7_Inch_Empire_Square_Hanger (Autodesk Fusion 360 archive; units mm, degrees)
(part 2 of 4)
sketch "Angular_Hip_Valley" plane through (0, 0, 0) normal (0, 1, 0) x axis (1, 0, 0)
  line L1 (38.1, -88.7211) -> (122.0586, -4.7625)
  line L2 (0, 1.5875) -> (0, -176.2125)
  line L3 (177.8, 1.5875) -> (0, 1.5875)
  line L4 (0, -176.2125) -> (177.8, 1.5875)
  line L5 (38.1, -97.7013) -> (38.1, -88.7211)
  line L6 (131.0388, -4.7625) -> (38.1, -97.7013)
  line L7 (122.0586, -4.7625) -> (131.0388, -4.7625)
  line L8 (113.4532, -13.3678) -> (0, 0)
  line L9 (116.5241, -10.297) -> (0, 0)
  line L10 (107.7616, -19.0595) -> (0, 0)
  line L11 (102.6349, -24.1862) -> (0, 0)
  line L12 (97.9544, -28.8667) -> (0, 0)
  line L13 (93.6966, -33.1245) -> (0, 0)
  line L14 (89.7798, -37.0412) -> (0, 0)
  line L15 (86.1898, -40.6313) -> (0, 0)
  line L16 (82.8697, -43.9514) -> (0, 0)
  line L17 (79.7978, -47.0233) -> (0, 0)
  line L18 (76.9467, -49.8744) -> (0, 0)
  line L19 (74.2837, -52.5374) -> (0, 0)
  line L20 (71.815, -55.0061) -> (0, 0)
  line L21 (69.4939, -57.3271) -> (0, 0)
  line L22 (67.3222, -59.4989) -> (0, 0)
  line L23 (65.2814, -61.5396) -> (0, 0)
  line L24 (63.3552, -63.4659) -> (0, 0)
  line L25 (61.5396, -65.2814) -> (0, 0)
  line L26 (59.832, -66.9891) -> (0, 0)
  line L27 (58.2084, -68.6127) -> (0, 0)
  line L28 (56.6787, -70.1424) -> (0, 0)
  line L29 (55.2312, -71.5899) -> (0, 0)
  line L30 (53.8432, -72.9778) -> (0, 0)
  line L31 (52.526, -74.2951) -> (0, 0)
  line L32 (36.3039, -86.925) -> (120.2625, -2.9664)
  line L33 (34.5079, -85.129) -> (118.4665, -1.1704)
  line L34 (107.0263, -12.6106) -> (113.4532, -13.3678)
  line L35 (109.9232, -9.7137) -> (116.5241, -10.297)
  line L36 (101.6571, -17.9798) -> (107.7616, -19.0595)
  line L37 (96.8208, -22.8161) -> (102.6349, -24.1862)
  line L38 (92.4054, -27.2315) -> (97.9544, -28.8667)
  line L39 (88.3888, -31.2481) -> (93.6966, -33.1245)
  line L40 (84.694, -34.9429) -> (89.7798, -37.0412)
  line L41 (81.3072, -38.3296) -> (86.1898, -40.6313)
  line L42 (78.1753, -41.4616) -> (82.8697, -43.9514)
  line L43 (75.2774, -44.3595) -> (79.7978, -47.0233)
  line L44 (72.5878, -47.0491) -> (76.9467, -49.8744)
  line L45 (70.0756, -49.5613) -> (74.2837, -52.5374)
  line L46 (67.7468, -51.8901) -> (71.815, -55.0061)
  line L47 (65.5572, -54.0797) -> (69.4939, -57.3271)
  line L48 (63.5085, -56.1284) -> (67.3222, -59.4989)
  line L49 (61.5834, -58.0535) -> (65.2814, -61.5396)
  line L50 (59.7662, -59.8706) -> (63.3552, -63.4659)
  line L51 (58.0535, -61.5834) -> (61.5396, -65.2814)
  line L52 (56.4427, -63.1942) -> (59.832, -66.9891)
  line L53 (54.911, -64.7259) -> (58.2084, -68.6127)
  line L54 (53.4679, -66.169) -> (56.6787, -70.1424)
  line L55 (52.1025, -67.5344) -> (55.2312, -71.5899)
  line L56 (50.7931, -68.8438) -> (53.8432, -72.9778)
  line L57 (49.5505, -70.0864) -> (52.526, -74.2951)
  line L58 (117.1566, -10.3529) -> (109.9232, -9.7137)
  line L59 (109.9511, -9.3974) -> (117.1846, -10.0366)
  line L60 (117.1287, -10.6692) -> (109.8952, -10.03)
  line L61 (114.0839, -13.4422) -> (107.0263, -12.6106)
  line L62 (107.0635, -12.2953) -> (114.121, -13.1268)
  line L63 (114.0467, -13.7575) -> (106.9892, -12.9259)
  line L64 (108.3869, -19.1701) -> (101.6571, -17.9798)
  line L65 (101.7124, -17.6671) -> (108.4422, -18.8574)
  line L66 (108.3316, -19.4827) -> (101.6018, -18.2924)
  line L67 (103.2529, -24.3319) -> (96.8208, -22.8161)
  line L68 (96.8936, -22.5071) -> (103.3258, -24.0228)
  line L69 (103.1801, -24.6409) -> (96.748, -23.1251)
  line L70 (98.5635, -29.0462) -> (92.4054, -27.2315)
  line L71 (92.4952, -26.9269) -> (98.6532, -28.7417)
  line L72 (98.4737, -29.3508) -> (92.3157, -27.536)
  line L73 (94.2953, -33.3362) -> (88.3888, -31.2481)
  line L74 (88.4947, -30.9487) -> (94.4011, -33.0368)
  line L75 (94.1895, -33.6355) -> (88.283, -31.5474)
  line L76 (90.3668, -37.2834) -> (84.694, -34.9429)
  line L77 (84.8151, -34.6494) -> (90.4879, -36.9899)
  line L78 (90.2458, -37.5769) -> (84.5729, -35.2364)
  line L79 (86.7641, -40.9021) -> (81.3072, -38.3296)
  line L80 (81.4426, -38.0425) -> (86.8995, -40.6149)
  line L81 (86.6287, -41.1893) -> (81.1719, -38.6168)
  line L82 (83.4307, -44.2489) -> (78.1753, -41.4616)
  line L83 (78.3241, -41.1811) -> (83.5795, -43.9684)
  line L84 (83.2819, -44.5294) -> (78.0265, -41.7421)
  line L85 (80.3449, -47.3457) -> (75.2774, -44.3595)
  line L86 (75.4386, -44.0859) -> (80.5061, -47.0721)
  line L87 (80.1837, -47.6192) -> (75.1162, -44.633)
  line L88 (77.4796, -50.2198) -> (72.5878, -47.0491)
  line L89 (72.7605, -46.7826) -> (77.6523, -49.9533)
  line L90 (77.3069, -50.4862) -> (72.4151, -47.3155)
  line L91 (74.8021, -52.9041) -> (70.0756, -49.5613)
  line L92 (70.259, -49.302) -> (74.9855, -52.6449)
  line L93 (74.6188, -53.1633) -> (69.8923, -49.8205)
  line L94 (72.3191, -55.3922) -> (67.7468, -51.8901)
  line L95 (67.9399, -51.638) -> (72.5122, -55.1402)
  line L96 (72.1261, -55.6443) -> (67.5537, -52.1421)
  line L97 (69.9838, -57.7312) -> (65.5572, -54.0797)
  line L98 (65.7593, -53.8347) -> (70.1858, -57.4863)
  line L99 (69.7817, -57.9761) -> (65.3552, -54.3246)
  line L100 (67.798, -59.9194) -> (63.5085, -56.1284)
  line L101 (63.7188, -55.8904) -> (68.0083, -59.6815)
  line L102 (67.5878, -60.1573) -> (63.2983, -56.3663)
  line L103 (65.7435, -61.9752) -> (61.5834, -58.0535)
  line L104 (61.8012, -57.8225) -> (65.9613, -61.7442)
  line L105 (65.5257, -62.2062) -> (61.3656, -58.2846)
  line L106 (63.8038, -63.9153) -> (59.7662, -59.8706)
  line L107 (59.9909, -59.6463) -> (64.0285, -63.691)
  line L108 (63.5791, -64.1396) -> (59.5415, -60.095)
  line L109 (61.9752, -65.7435) -> (58.0535, -61.5834)
  line L110 (58.2846, -61.3656) -> (62.2062, -65.5257)
  line L111 (61.7442, -65.9613) -> (57.8225, -61.8012)
  line L112 (60.255, -67.4627) -> (56.4427, -63.1942)
  line L113 (56.6795, -62.9827) -> (60.4918, -67.2512)
  line L114 (60.0182, -67.6742) -> (56.2059, -63.4057)
  line L115 (58.6192, -69.0969) -> (54.911, -64.7259)
  line L116 (55.1531, -64.5205) -> (58.8613, -68.8915)
  line L117 (58.3771, -69.3023) -> (54.6689, -64.9313)
  line L118 (57.0778, -70.6363) -> (53.4679, -66.169)
  line L119 (53.7149, -65.9694) -> (57.3247, -70.4368)
  line L120 (56.8308, -70.8359) -> (53.221, -66.3685)
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  point P8 (0, 0)
  point P17 (0, 0)
  point P18 (113.4532, -13.3678)
  point P19 (0, 0)
  point P20 (116.5241, -10.297)
  point P21 (107.7616, -19.0595)
  point P22 (0, 0)
  point P23 (102.6349, -24.1862)
  point P24 (97.9544, -28.8667)
  point P25 (93.6966, -33.1245)
  point P26 (89.7798, -37.0412)
  point P27 (0, 0)
  point P28 (86.1898, -40.6313)
  point P29 (82.8697, -43.9514)
  point P31 (76.9467, -49.8744)
  point P32 (0, 0)
  point P33 (74.2837, -52.5374)
  point P34 (0, 0)
  point P35 (71.815, -55.0061)
  point P36 (69.4939, -57.3271)
  point P37 (67.3222, -59.4989)
  point P38 (65.2814, -61.5396)
  point P39 (63.3552, -63.4659)
  point P40 (61.5396, -65.2814)
  point P41 (59.832, -66.9891)
  point P42 (58.2084, -68.6127)
  point P43 (0, 0)
  point P44 (56.6787, -70.1424)
  point P45 (55.2312, -71.5899)
  point P46 (53.8432, -72.9778)
  point P47 (52.526, -74.2951)
  point P52 (107.0263, -12.6106)
  point P53 (109.9232, -9.7137)
  point P54 (101.6571, -17.9798)
  point P55 (96.8208, -22.8161)
  point P56 (92.4054, -27.2315)
  point P57 (88.3888, -31.2481)
  point P58 (84.694, -34.9429)
  point P59 (81.3072, -38.3296)
  point P60 (78.1753, -41.4616)
  point P61 (75.2774, -44.3595)
  point P30 (79.7978, -47.0233)
  point P62 (72.5878, -47.0491)
  point P63 (70.0756, -49.5613)
  point P64 (67.7468, -51.8901)
  point P65 (65.5572, -54.0797)
  point P66 (63.5085, -56.1284)
  point P67 (61.5834, -58.0535)
  point P68 (59.7662, -59.8706)
  point P69 (58.0535, -61.5834)
  point P70 (56.4427, -63.1942)
  point P71 (54.911, -64.7259)
  point P72 (53.4679, -66.169)
  point P73 (52.1025, -67.5344)
  point P74 (50.7931, -68.8438)
  point P75 (49.5505, -70.0864)
  point P82 (116.5241, -10.297)
  point P89 (113.4532, -13.3678)
  point P96 (107.7616, -19.0595)
  point P103 (102.6349, -24.1862)
  point P110 (97.9544, -28.8667)
  point P117 (93.6966, -33.1245)
  point P124 (89.7798, -37.0412)
  point P131 (86.1898, -40.6313)
  point P138 (82.8697, -43.9514)
  point P145 (79.7978, -47.0233)
  point P152 (76.9467, -49.8744)
  point P159 (74.2837, -52.5374)
  point P166 (71.815, -55.0061)
  point P173 (69.4939, -57.3271)
  point P180 (67.3222, -59.4989)
  point P187 (65.2814, -61.5396)
  point P194 (63.3552, -63.4659)
  point P201 (61.5396, -65.2814)
  point P208 (59.832, -66.9891)
  point P215 (58.2084, -68.6127)
  point P222 (56.6787, -70.1424)
  point P83 (107.0263, -12.6106)
  point P76 (109.9232, -9.7137)
  point P90 (101.6571, -17.9798)
  point P97 (96.8208, -22.8161)
  point P104 (92.4054, -27.2315)
  point P111 (88.3888, -31.2481)
  point P118 (84.694, -34.9429)
  point P125 (81.3072, -38.3296)
  point P132 (78.1753, -41.4616)
  point P139 (75.2774, -44.3595)
  point P146 (72.5878, -47.0491)
  point P153 (70.0756, -49.5613)
  point P160 (67.7468, -51.8901)
  point P167 (65.5572, -54.0797)
  point P174 (63.5085, -56.1284)
  point P181 (61.5834, -58.0535)
  point P188 (59.7662, -59.8706)
  point P195 (58.0535, -61.5834)
  point P202 (56.4427, -63.1942)
  point P209 (54.911, -64.7259)
  point P216 (53.4679, -66.169)
  point P229 (55.2312, -71.5899)
  point P223 (52.1025, -67.5344)
  point P243 (53.8432, -72.9778)
  point P237 (50.7931, -68.8438)
  point P236 (52.526, -74.2951)
  point P230 (49.5505, -70.0864)
  point P78 (117.1566, -10.3529)
  point P85 (114.0839, -13.4422)
  point P92 (108.3869, -19.1701)
  point P99 (103.2529, -24.3319)
  point P106 (98.5635, -29.0462)
  point P113 (94.2953, -33.3362)
  point P120 (90.3668, -37.2834)
  point P127 (86.7641, -40.9021)
  point P134 (83.4307, -44.2489)
  point P141 (80.3449, -47.3457)
  point P148 (77.4796, -50.2198)
  point P155 (74.8021, -52.9041)
  point P162 (72.3191, -55.3922)
  point P169 (69.9838, -57.7312)
  point P176 (67.798, -59.9194)
  point P183 (65.7435, -61.9752)
  point P190 (63.8038, -63.9153)
  point P197 (61.9752, -65.7435)
  point P204 (60.255, -67.4627)
  point P211 (58.6192, -69.0969)
  point P218 (57.0778, -70.6363)
  point P225 (55.6191, -72.0926)
  point P232 (52.8926, -74.8136)
  point P239 (54.2202, -73.4888)
  coincident P8 P17
  coincident L1 P18
  coincident P8 P19
  coincident L1 P20
  coincident L1 P21
  coincident P8 P22
  coincident L1 P23
  coincident L1 P24
  coincident L1 P25
  coincident L1 P26
  coincident P8 P27
  coincident L1 P28
  coincident L1 P29
  coincident L1 P31
  coincident P8 P32
  coincident L1 P33
  coincident P8 P34
  coincident L1 P35
  coincident L1 P36
  coincident L1 P37
  coincident L1 P38
  coincident L1 P39
  coincident L1 P40
  coincident L1 P41
  coincident L1 P42
  coincident P8 P43
  coincident L1 P44
  coincident L1 P45
  coincident L1 P46
  coincident L1 P47
  coincident L8 P52
  coincident L33 P52
  coincident L33 P53
  coincident L9 P53
  coincident L10 P54
  coincident L33 P54
  coincident L11 P55
  coincident L33 P55
  coincident L12 P56
  coincident L33 P56
  coincident L13 P57
  coincident L33 P57
  coincident L14 P58
  coincident L33 P58
  coincident L15 P59
  coincident L33 P59
  coincident L16 P60
  coincident L33 P60
  coincident L17 P61
  coincident L33 P61
  coincident L1 P30
  coincident L18 P62
  coincident L33 P62
  coincident L19 P63
  coincident L33 P63
  coincident L20 P64
  coincident L33 P64
  coincident L21 P65
  coincident L33 P65
  coincident L22 P66
  coincident L33 P66
  coincident L23 P67
  coincident L33 P67
  coincident L24 P68
  coincident L33 P68
  coincident L25 P69
  coincident L33 P69
  coincident L26 P70
  coincident L33 P70
  coincident L27 P71
  coincident L33 P71
  coincident L28 P72
  coincident L33 P72
  coincident L29 P73
  coincident L33 P73
  coincident L30 P74
  coincident L33 P74
  coincident L31 P75
  coincident L33 P75
  parallel L59 L60
  coincident P82 L58
  parallel L62 L63
  coincident P89 L61
  parallel L65 L66
  coincident P96 L64
  parallel L68 L69
  coincident P103 L67
  parallel L71 L72
  coincident P110 L70
  parallel L74 L75
  coincident P117 L73
  parallel L77 L78
  coincident P124 L76
  parallel L80 L81
  coincident P131 L79
  parallel L83 L84
  coincident P138 L82
  parallel L86 L87
  coincident P145 L85
  parallel L89 L90
  coincident P152 L88
  parallel L92 L93
  coincident P159 L91
  parallel L95 L96
  coincident P166 L94
  parallel L98 L99
  coincident P173 L97
  parallel L101 L102
  coincident P180 L100
  parallel L104 L105
  coincident P187 L103
  parallel L107 L108
  coincident P194 L106
  parallel L110 L111
  coincident P201 L109
  parallel L113 L114
  coincident P208 L112
  parallel L116 L117
  coincident P215 L115
  parallel L119 L120
  coincident P222 L118
  coincident P52 P83
  coincident P18 P89
  coincident P53 P76
  coincident P20 P82
  coincident P54 P90
  coincident P21 P96
  coincident P55 P97
  coincident P23 P103
  coincident P56 P104
  coincident P24 P110
  coincident P57 P111
  coincident P25 P117
  coincident P58 P118
  coincident P26 P124
  coincident P59 P125
  coincident P28 P131
  coincident P60 P132
  coincident P29 P138
  coincident P61 P139
  coincident P30 P145
  coincident P62 P146
  coincident P31 P152
  coincident P63 P153
  coincident P33 P159
  coincident P64 P160
  coincident P35 P166
  coincident P65 P167
  coincident P36 P173
  coincident P66 P174
  coincident P37 P180
  coincident P67 P181
  coincident P38 P187
  coincident P68 P188
  coincident P39 P194
  coincident P40 P201
  coincident P69 P195
  coincident P41 P208
  coincident P70 P202
  coincident P42 P215
  coincident P71 P209
  coincident P44 P222
  coincident P72 P216
  coincident P45 P229
  coincident P73 P223
  coincident P46 P243
  coincident P74 P237
  coincident P47 P236
  coincident P75 P230
  dimension "d777" angle L3 L8 = 6.72
  dimension "d778" angle L3 L10 = 10.03
  dimension "d779" angle L3 L11 = 13.26
  dimension "d780" angle L3 L12 = 16.42
  dimension "d781" angle L3 L13 = 19.47
  dimension "d782" angle L3 L14 = 22.42
  dimension "d783" angle L3 L15 = 25.24
  dimension "d784" angle L3 L16 = 27.94
  dimension "d785" angle L3 L17 = 30.51
  dimension "d786" angle L3 L18 = 32.95
  dimension "d787" angle L3 L19 = 35.27
  dimension "d788" angle L3 L20 = 37.45
  dimension "d789" angle L3 L21 = 39.52
  dimension "d790" angle L3 L22 = 41.47
  dimension "d791" angle L3 L23 = 43.31
  dimension "d792" angle L3 L24 = 45.05
  dimension "d793" angle L3 L25 = 46.69
  dimension "d794" angle L3 L26 = 48.23
  dimension "d795" angle L3 L27 = 49.69
  dimension "d796" angle L3 L28 = 51.06
  dimension "d797" angle L3 L29 = 52.35
  dimension "d798" angle L3 L30 = 53.58
  dimension "d799" angle L3 L31 = 54.74
  dimension "d850" = 2.54
  dimension "d851" = 5.08
  dimension "d852" angle L3 L9 = 5.05
  dimension "d855" diameter = 0.635
  dimension "d856" distance P78 P82 = 0.635
  dimension "d857" diameter = 0.635
  dimension "d858" distance P85 P89 = 0.635
  dimension "d859" diameter = 0.635
  dimension "d860" distance P92 P96 = 0.635
  dimension "d861" diameter = 0.635
  dimension "d862" distance P99 P103 = 0.635
  dimension "d863" diameter = 0.635
  dimension "d864" distance P106 P110 = 0.635
  dimension "d865" diameter = 0.635
  dimension "d866" distance P113 P117 = 0.635
  dimension "d867" diameter = 0.635
  dimension "d868" distance P120 P124 = 0.635
  dimension "d869" diameter = 0.635
  dimension "d870" distance P127 P131 = 0.635
  dimension "d871" diameter = 0.635
  dimension "d872" distance P134 P138 = 0.635
  dimension "d873" diameter = 0.635
  dimension "d874" distance P141 P145 = 0.635
  dimension "d875" diameter = 0.635
  dimension "d876" distance P148 P152 = 0.635
  dimension "d877" diameter = 0.635
  dimension "d878" distance P155 P159 = 0.635
  dimension "d879" diameter = 0.635
  dimension "d880" distance P162 P166 = 0.635
  dimension "d881" diameter = 0.635
  dimension "d882" distance P169 P173 = 0.635
  dimension "d883" diameter = 0.635
  dimension "d884" distance P176 P180 = 0.635
  dimension "d885" diameter = 0.635
  dimension "d886" distance P183 P187 = 0.635
  dimension "d887" diameter = 0.635
  dimension "d888" distance P190 P194 = 0.635
  dimension "d889" diameter = 0.635
  dimension "d890" distance P197 P201 = 0.635
  dimension "d891" diameter = 0.635
  dimension "d892" distance P204 P208 = 0.635
  dimension "d893" diameter = 0.635
  dimension "d894" distance P211 P215 = 0.635
  dimension "d895" diameter = 0.635
  dimension "d896" distance P218 P222 = 0.635
  dimension "d897" diameter = 0.635
  dimension "d898" distance P225 P229 = 0.635
  dimension "d899" diameter = 0.635
  dimension "d900" distance P232 P236 = 0.635
  dimension "d901" diameter = 0.635
  dimension "d902" distance P239 P243 = 0.635
sketch "Angular_Degree_Scale" plane through (0, 0, 0) normal (0, 1, 0) x axis (1, 0, 0)
  line L1 (0, 1.5875) -> (0, -176.2125)
  line L2 (177.8, 1.5875) -> (0, 1.5875)
  line L3 (0, -176.2125) -> (177.8, 1.5875)
  line L4 (176.2125, 0) -> (0, 0)
  line L5 (173.1831, 0) -> (176.2125, 0)
  line L6 (173.1561, -3.0564) -> (176.1851, -3.1099)
  line L7 (170.2021, -6.0104) -> (176.1027, -6.2188)
  line L8 (167.3437, -8.8688) -> (175.9656, -9.3258)
  line L9 (164.5746, -11.6379) -> (175.7736, -12.4298)
  line L10 (161.8891, -14.3234) -> (175.5268, -15.53)
  line L11 (159.2818, -16.9307) -> (175.2254, -18.6254)
  line L12 (156.7478, -19.4647) -> (174.8694, -21.715)
  line L13 (154.2826, -21.9299) -> (174.4589, -24.7978)
  line L14 (151.8819, -24.3306) -> (173.9941, -27.8728)
  line L15 (149.5418, -26.6707) -> (173.4751, -30.9392)
  line L16 (147.2585, -28.954) -> (172.902, -33.996)
  line L17 (145.0288, -31.1837) -> (172.2751, -37.0421)
  line L18 (142.8493, -33.3632) -> (171.5946, -40.0768)
  line L19 (140.7171, -35.4954) -> (170.8606, -43.0989)
  line L20 (138.6294, -37.5831) -> (170.0733, -46.1076)
  line L21 (136.5836, -39.6289) -> (169.2331, -49.102)
  line L22 (134.5771, -41.6354) -> (168.3402, -52.081)
  line L23 (132.6076, -43.6049) -> (167.3948, -55.0439)
  line L24 (130.6729, -45.5396) -> (166.3973, -57.9896)
  line L25 (128.7709, -47.4416) -> (165.3479, -60.9172)
  line L26 (126.8997, -49.3128) -> (164.2471, -63.8259)
  line L27 (125.0573, -51.1552) -> (163.0951, -66.7146)
  line L28 (123.2421, -52.9704) -> (161.8923, -69.5826)
  line L29 (121.4521, -54.7604) -> (160.639, -72.4289)
  line L30 (119.686, -56.5265) -> (159.3357, -75.2527)
  line L31 (117.9421, -58.2704) -> (157.9828, -78.053)
  line L32 (116.2188, -59.9937) -> (156.5807, -80.829)
  line L33 (114.5149, -61.6976) -> (155.1298, -83.5798)
  line L34 (112.8289, -63.3836) -> (153.6306, -86.3046)
  line L35 (111.1596, -65.0529) -> (152.0835, -89.0025)
  line L36 (109.5055, -66.707) -> (150.4891, -91.6727)
  line L37 (107.8656, -68.3469) -> (148.8478, -94.3143)
  line L38 (106.2387, -69.9738) -> (147.1601, -96.9266)
  line L39 (104.6235, -71.589) -> (145.4265, -99.5086)
  line L40 (103.019, -73.1935) -> (143.6477, -102.0597)
  line L41 (101.424, -74.7885) -> (141.8241, -104.579)
  line L42 (99.8375, -76.375) -> (139.9564, -107.0656)
  line L43 (98.2585, -77.954) -> (138.0451, -109.519)
  line L44 (96.6858, -79.5267) -> (136.0907, -111.9382)
  line L45 (95.1186, -81.0939) -> (134.094, -114.3226)
  line L46 (93.5558, -82.6567) -> (132.0555, -116.6713)
  line L47 (91.9963, -84.2162) -> (129.9758, -118.9837)
  line L48 (90.4393, -85.7732) -> (127.8557, -121.2591)
  line L49 (88.8838, -87.3287) -> (125.6958, -123.4966)
  line L50 (87.3287, -88.8838) -> (123.4966, -125.6958)
  line L51 (85.7732, -90.4393) -> (121.2591, -127.8557)
  line L52 (84.2162, -91.9963) -> (118.9837, -129.9758)
  line L53 (82.6567, -93.5558) -> (116.6713, -132.0555)
  line L54 (81.0939, -95.1186) -> (114.3226, -134.094)
  line L55 (79.5267, -96.6858) -> (111.9382, -136.0907)
  line L56 (77.954, -98.2585) -> (109.519, -138.0451)
  line L57 (76.375, -99.8375) -> (107.0656, -139.9564)
  line L58 (74.7885, -101.424) -> (104.579, -141.8241)
  line L59 (73.1935, -103.019) -> (102.0597, -143.6477)
  line L60 (71.589, -104.6235) -> (99.5086, -145.4265)
  line L61 (69.9738, -106.2387) -> (96.9266, -147.1601)
  line L62 (68.3469, -107.8656) -> (94.3143, -148.8478)
  line L63 (66.707, -109.5055) -> (91.6727, -150.4891)
  line L64 (65.0529, -111.1596) -> (89.0025, -152.0835)
  line L65 (63.3836, -112.8289) -> (86.3046, -153.6306)
  line L66 (61.6976, -114.5149) -> (83.5798, -155.1298)
  line L67 (59.9937, -116.2188) -> (80.829, -156.5807)
  line L68 (58.2704, -117.9421) -> (78.053, -157.9828)
  line L69 (56.5265, -119.686) -> (75.2527, -159.3357)
  line L70 (54.7604, -121.4521) -> (72.4289, -160.639)
  line L71 (52.9704, -123.2421) -> (69.5826, -161.8923)
  line L72 (51.1552, -125.0573) -> (66.7146, -163.0951)
  line L73 (49.3128, -126.8997) -> (63.8259, -164.2471)
  line L74 (47.4416, -128.7709) -> (60.9172, -165.3479)
  line L75 (45.5396, -130.6729) -> (57.9896, -166.3973)
  line L76 (43.6049, -132.6076) -> (55.0439, -167.3948)
  line L77 (41.6354, -134.5771) -> (52.081, -168.3402)
  line L78 (39.6289, -136.5836) -> (49.102, -169.2331)
  line L79 (37.5831, -138.6294) -> (46.1076, -170.0733)
  line L80 (35.4954, -140.7171) -> (43.0989, -170.8606)
  line L81 (33.3632, -142.8493) -> (40.0768, -171.5946)
  line L82 (31.1837, -145.0288) -> (37.0421, -172.2751)
  line L83 (28.954, -147.2585) -> (33.996, -172.902)
  line L84 (26.6707, -149.5418) -> (30.9392, -173.4751)
  line L85 (24.3306, -151.8819) -> (27.8728, -173.9941)
  line L86 (21.9299, -154.2826) -> (24.7978, -174.4589)
  line L87 (19.4647, -156.7478) -> (21.715, -174.8694)
  line L88 (16.9307, -159.2818) -> (18.6254, -175.2254)
  line L89 (14.3234, -161.8891) -> (15.53, -175.5268)
  line L90 (11.6379, -164.5746) -> (12.4298, -175.7736)
  line L91 (8.8688, -167.3437) -> (9.3258, -175.9656)
  line L92 (6.0104, -170.2021) -> (6.2188, -176.1027)
  line L93 (3.0564, -173.1561) -> (3.1099, -176.1851)
  line L94 (0, -169.0283) -> (0, -176.2125)
  line L95 (-1.7961, -174.4164) -> (176.0039, 3.3836)
  line L96 (-3.5921, -172.6204) -> (174.2079, 5.1796)
  line L97 (169.6263, -2.9941) -> (173.1561, -3.0564)
  line L98 (166.7325, -5.8879) -> (170.2021, -6.0104)
  line L99 (163.9324, -8.688) -> (167.3437, -8.8688)
  line L100 (161.2197, -11.4007) -> (164.5746, -11.6379)
  line L101 (155.2888, -13.7395) -> (161.8891, -14.3234)
  line L102 (156.0348, -16.5856) -> (159.2818, -16.9307)
  line L103 (153.5525, -19.0679) -> (156.7478, -19.4647)
  line L104 (151.1376, -21.4828) -> (154.2826, -21.9299)
  line L105 (148.7858, -23.8346) -> (151.8819, -24.3306)
  line L106 (143.4449, -25.5834) -> (149.5418, -26.6707)
  line L107 (144.2567, -28.3637) -> (147.2585, -28.954)
  line L108 (142.0724, -30.548) -> (145.0288, -31.1837)
  line L109 (139.9373, -32.6831) -> (142.8493, -33.3632)
  line L110 (137.8486, -34.7718) -> (140.7171, -35.4954)
  line L111 (132.9775, -36.0508) -> (138.6294, -37.5831)
  line L112 (133.7993, -38.8211) -> (136.5836, -39.6289)
  line L113 (131.8337, -40.7867) -> (134.5771, -41.6354)
  line L114 (129.9044, -42.716) -> (132.6076, -43.6049)
  line L115 (128.0091, -44.6113) -> (130.6729, -45.5396)
  line L116 (123.5209, -45.5074) -> (128.7709, -47.4416)
  line L117 (124.3129, -48.3075) -> (126.8997, -49.3128)
  line L118 (122.508, -50.1124) -> (125.0573, -51.1552)
  line L119 (120.7298, -51.8906) -> (123.2421, -52.9704)
  line L120 (118.9763, -53.6441) -> (121.4521, -54.7604)
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  point P6 (0, 0)
  point P9 (0, 0)
  point P10 (176.2053, 1.5875)
  point P11 (0, 0)
  point P12 (176.2125, 0)
  point P13 (173.1831, 0)
  point P15 (173.1561, -3.0564)
  point P110 (170.2021, -6.0104)
  point P111 (167.3437, -8.8688)
  point P112 (164.5746, -11.6379)
  point P113 (161.8891, -14.3234)
  point P114 (159.2818, -16.9307)
  point P115 (156.7478, -19.4647)
  point P116 (154.2826, -21.9299)
  point P117 (151.8819, -24.3306)
  point P118 (149.5418, -26.6707)
  point P119 (147.2585, -28.954)
  point P120 (145.0288, -31.1837)
  point P121 (142.8493, -33.3632)
  point P122 (140.7171, -35.4954)
  point P123 (138.6294, -37.5831)
  point P124 (136.5836, -39.6289)
  point P125 (134.5771, -41.6354)
  point P126 (132.6076, -43.6049)
  point P127 (130.6729, -45.5396)
  point P128 (128.7709, -47.4416)
  point P129 (126.8997, -49.3128)
  point P130 (125.0573, -51.1552)
  point P131 (123.2421, -52.9704)
  point P132 (121.4521, -54.7604)
  point P133 (119.686, -56.5265)
  point P134 (116.2188, -59.9937)
  point P135 (114.5149, -61.6976)
  point P136 (117.9421, -58.2704)
  point P137 (112.8289, -63.3836)
  point P138 (111.1596, -65.0529)
  point P139 (109.5055, -66.707)
  point P140 (107.8656, -68.3469)
  point P141 (106.2387, -69.9738)
  point P142 (104.6235, -71.589)
  point P143 (103.019, -73.1935)
  point P144 (101.424, -74.7885)
  point P145 (99.8375, -76.375)
  point P146 (96.6858, -79.5267)
  point P147 (98.2585, -77.954)
  point P148 (95.1186, -81.0939)
  point P149 (93.5558, -82.6567)
  point P150 (91.9963, -84.2162)
  point P151 (90.4393, -85.7732)
  point P152 (88.8838, -87.3287)
  point P153 (87.3287, -88.8838)
  point P154 (85.7732, -90.4393)
  point P155 (84.2162, -91.9963)
  point P156 (82.6567, -93.5558)
  point P157 (81.0939, -95.1186)
  point P158 (79.5267, -96.6858)
  point P159 (77.954, -98.2585)
  point P160 (76.375, -99.8375)
  point P161 (74.7885, -101.424)
  point P162 (73.1935, -103.019)
  point P163 (69.9738, -106.2387)
  point P164 (68.3469, -107.8656)
  point P165 (66.707, -109.5055)
  point P166 (65.0529, -111.1596)
  point P167 (63.3836, -112.8289)
  point P168 (61.6976, -114.5149)
  point P169 (59.9937, -116.2188)
  point P170 (58.2704, -117.9421)
  point P171 (56.5265, -119.686)
  point P172 (52.9704, -123.2421)
  point P173 (54.7604, -121.4521)
  point P174 (51.1552, -125.0573)
  point P175 (49.3128, -126.8997)
  point P176 (47.4416, -128.7709)
  point P177 (45.5396, -130.6729)
  point P178 (43.6049, -132.6076)
  point P179 (41.6354, -134.5771)
  point P180 (39.6289, -136.5836)
  point P181 (37.5831, -138.6294)
  point P182 (35.4954, -140.7171)
  point P183 (33.3632, -142.8493)
  point P184 (31.1837, -145.0288)
  point P185 (28.954, -147.2585)
  point P186 (26.6707, -149.5418)
  point P187 (24.3306, -151.8819)
  point P188 (21.9299, -154.2826)
  point P189 (19.4647, -156.7478)
  point P190 (16.9307, -159.2818)
  point P191 (14.3234, -161.8891)
  point P192 (11.6379, -164.5746)
  point P193 (8.8688, -167.3437)
  point P194 (6.0104, -170.2021)
  point P195 (71.589, -104.6235)
  point P196 (169.6263, -2.9941)
  point P197 (166.7325, -5.8879)
  point P198 (163.9324, -8.688)
  point P199 (161.2197, -11.4007)
  point P200 (155.2888, -13.7395)
  point P201 (156.0348, -16.5856)
  point P202 (153.5525, -19.0679)
  point P203 (151.1376, -21.4828)
  point P204 (148.7858, -23.8346)
  point P205 (143.4449, -25.5834)
  point P206 (144.2567, -28.3637)
  point P207 (142.0724, -30.548)
  point P208 (139.9373, -32.6831)
  point P209 (137.8486, -34.7718)
  point P210 (132.9775, -36.0508)
  point P211 (133.7993, -38.8211)
  point P212 (131.8337, -40.7867)
  point P213 (129.9044, -42.716)
  point P214 (128.0091, -44.6113)
  point P215 (123.5209, -45.5074)
  point P216 (124.3129, -48.3075)
  point P217 (122.508, -50.1124)
  point P218 (120.7298, -51.8906)
  point P219 (118.9763, -53.6441)
  point P220 (114.8064, -54.2219)
  point P221 (115.5378, -57.0826)
  point P222 (113.8497, -58.7707)
  point P223 (112.1805, -60.4399)
  point P224 (110.5289, -62.0915)
  point P225 (106.6276, -62.4007)
  point P226 (107.2733, -65.3471)
  point P227 (105.6668, -66.9536)
  point P228 (104.073, -68.5474)
  point P229 (102.4907, -70.1297)
  point P230 (98.8189, -70.2094)
  point P231 (99.3565, -73.2639)
  point P232 (97.8023, -74.8181)
  point P233 (96.2555, -76.3649)
  point P234 (94.7149, -77.9055)
  point P235 (91.2406, -77.7877)
  point P236 (91.6486, -80.9718)
  point P237 (90.121, -82.4994)
  point P238 (88.5957, -84.0247)
  point P239 (87.0719, -85.5485)
  point P240 (83.7683, -85.26)
  point P241 (84.0247, -88.5957)
  point P242 (82.4994, -90.121)
  point P243 (80.9718, -91.6486)
  point P244 (79.4408, -93.1796)
  point P245 (76.2844, -92.7439)
  point P246 (76.3649, -96.2555)
  point P247 (74.8181, -97.8023)
  point P248 (73.2639, -99.3565)
  point P249 (71.7015, -100.9189)
  point P250 (68.6703, -100.358)
  point P251 (68.5474, -104.073)
  point P252 (66.9536, -105.6668)
  point P253 (65.3471, -107.2733)
  point P254 (63.7268, -108.8936)
  point P255 (60.7994, -108.2289)
  point P256 (60.4399, -112.1805)
  point P257 (58.7707, -113.8497)
  point P258 (57.0826, -115.5378)
  point P259 (55.3742, -117.2462)
  point P260 (52.5278, -116.5005)
  point P261 (51.8906, -120.7298)
  point P262 (50.1124, -122.508)
  point P263 (48.3075, -124.3129)
  point P264 (46.4745, -126.1459)
  point P265 (43.6829, -125.3453)
  point P266 (42.716, -129.9044)
  point P267 (40.7867, -131.8337)
  point P268 (38.8211, -133.7993)
  point P269 (36.8169, -135.8035)
  point P270 (34.0482, -134.9801)
  point P271 (32.6831, -139.9373)
  point P272 (30.548, -142.0724)
  point P273 (28.3637, -144.2567)
  point P274 (26.127, -146.4934)
  point P275 (23.3386, -145.6897)
  point P276 (21.4828, -151.1376)
  point P277 (19.0679, -153.5525)
  point P278 (16.5856, -156.0348)
  point P279 (14.0314, -158.589)
  point P280 (11.1634, -157.8649)
  point P281 (8.688, -163.9324)
  point P282 (5.8879, -166.7325)
  point P283 (2.9941, -169.6263)
  point P105 (0, -169.0283)
  point P284 (169.6263, -2.9941)
  point P289 (173.7911, -3.0676)
  point P290 (173.7911, -3.0676)
  point P293 (166.7325, -5.8879)
  point P295 (166.7325, -5.8879)
  point P296 (170.8371, -6.0328)
  point P298 (170.8371, -6.0328)
  point P301 (163.9324, -8.688)
  point P303 (163.9324, -8.688)
  point P304 (167.9787, -8.9025)
  point P306 (167.9787, -8.9025)
  point P309 (161.2197, -11.4007)
  point P311 (161.2197, -11.4007)
  point P312 (165.2096, -11.6828)
  point P314 (165.2096, -11.6828)
  point P317 (155.2888, -13.7395)
  point P319 (155.2888, -13.7395)
  point P320 (162.5241, -14.3796)
  point P322 (162.5241, -14.3796)
  point P325 (156.0348, -16.5856)
  point P327 (156.0348, -16.5856)
  point P328 (159.9168, -16.9982)
  point P330 (159.9168, -16.9982)
  point P333 (153.5525, -19.0679)
  point P335 (153.5525, -19.0679)
  point P336 (157.3828, -19.5435)
  point P338 (157.3828, -19.5435)
  point P341 (151.1376, -21.4828)
  point P343 (151.1376, -21.4828)
  point P344 (154.9176, -22.0201)
  point P346 (154.9176, -22.0201)
  point P349 (148.7858, -23.8346)
  point P351 (148.7858, -23.8346)
  point P352 (152.5169, -24.4323)
  point P354 (152.5169, -24.4323)
  point P357 (143.4449, -25.5834)
  point P359 (143.4449, -25.5834)
  point P360 (150.1768, -26.784)
  point P362 (150.1768, -26.784)
  point P364 (144.2567, -28.3637)
  point P368 (144.2567, -28.3637)
  point P369 (147.8935, -29.0788)
  point P371 (147.8935, -29.0788)
  point P363 (144.2567, -28.3637)
  point P373 (142.0724, -30.548)
  point P377 (142.0724, -30.548)
  point P378 (145.6638, -31.3202)
  point P380 (145.6638, -31.3202)
  point P372 (142.0724, -30.548)
  point P382 (139.9373, -32.6831)
  point P386 (139.9373, -32.6831)
  point P387 (143.4843, -33.5115)
  point P389 (143.4843, -33.5115)
  point P381 (139.9373, -32.6831)
  point P391 (137.8486, -34.7718)
  point P395 (137.8486, -34.7718)
  point P396 (141.3521, -35.6555)
  point P398 (141.3521, -35.6555)
  point P390 (137.8486, -34.7718)
  point P400 (132.9775, -36.0508)
  point P404 (132.9775, -36.0508)
  point P405 (139.2644, -37.7552)
  point P407 (139.2644, -37.7552)
  point P399 (132.9775, -36.0508)
  point P410 (99.3565, -73.2639)
  point P411 (99.3565, -73.2639)
  point P413 (102.059, -75.2567)
  point P417 (102.059, -75.2567)
  point P408 (99.3565, -73.2639)
  point P416 (99.3565, -73.2639)
  point P420 (133.7993, -38.8211)
  point P421 (133.7993, -38.8211)
  point P423 (137.2186, -39.8132)
  point P437 (137.2186, -39.8132)
  point P418 (133.7993, -38.8211)
  point P426 (133.7993, -38.8211)
  point P428 (97.8023, -74.8181)
  point P432 (97.8023, -74.8181)
  point P433 (100.4725, -76.8608)
  point P435 (100.4725, -76.8608)
  point P431 (97.8023, -74.8181)
  point P436 (97.8023, -74.8181)
  point P439 (131.8337, -40.7867)
  point P443 (131.8337, -40.7867)
  point P444 (135.2121, -41.8319)
  point P446 (135.2121, -41.8319)
  point P442 (131.8337, -40.7867)
  point P447 (131.8337, -40.7867)
  point P449 (129.9044, -42.716)
  point P453 (129.9044, -42.716)
  point P454 (133.2426, -43.8137)
  point P456 (133.2426, -43.8137)
  point P452 (129.9044, -42.716)
  point P457 (129.9044, -42.716)
  point P460 (128.0091, -44.6113)
  point P461 (128.0091, -44.6113)
  point P463 (131.3079, -45.7609)
  point P467 (131.3079, -45.7609)
  point P458 (128.0091, -44.6113)
  point P466 (128.0091, -44.6113)
  point P470 (123.5209, -45.5074)
  point P471 (123.5209, -45.5074)
  point P473 (129.4059, -47.6755)
  point P477 (129.4059, -47.6755)
  point P468 (123.5209, -45.5074)
  point P476 (123.5209, -45.5074)
  point P480 (124.3129, -48.3075)
  point P481 (124.3129, -48.3075)
  point P483 (127.5347, -49.5595)
  point P497 (127.5347, -49.5595)
  point P478 (124.3129, -48.3075)
  point P486 (124.3129, -48.3075)
  point P488 (76.3649, -96.2555)
  point P492 (76.3649, -96.2555)
  point P493 (78.589, -99.0589)
  point P495 (78.589, -99.0589)
  point P491 (76.3649, -96.2555)
  point P496 (76.3649, -96.2555)
  point P500 (122.508, -50.1124)
  point P501 (122.508, -50.1124)
  point P503 (125.6923, -51.4149)
  point P517 (125.6923, -51.4149)
  point P498 (122.508, -50.1124)
  point P506 (122.508, -50.1124)
  point P508 (76.2844, -92.7439)
  point P512 (76.2844, -92.7439)
  point P513 (80.1617, -97.4578)
  point P515 (80.1617, -97.4578)
  point P511 (76.2844, -92.7439)
  point P516 (76.2844, -92.7439)
  point P520 (79.4408, -93.1796)
  point P521 (79.4408, -93.1796)
  point P523 (81.7289, -95.8634)
  point P537 (81.7289, -95.8634)
  point P518 (79.4408, -93.1796)
  point P526 (79.4408, -93.1796)
  point P528 (120.7298, -51.8906)
  point P532 (120.7298, -51.8906)
  point P533 (123.8771, -53.2434)
  point P535 (123.8771, -53.2434)
  point P531 (120.7298, -51.8906)
  point P536 (120.7298, -51.8906)
  point P540 (118.9763, -53.6441)
  point P541 (118.9763, -53.6441)
  point P543 (122.0871, -55.0467)
  point P557 (122.0871, -55.0467)
  point P538 (118.9763, -53.6441)
  point P546 (118.9763, -53.6441)
  point P548 (80.9718, -91.6486)
  point P552 (80.9718, -91.6486)
  point P553 (83.2917, -94.2745)
  point P555 (83.2917, -94.2745)
  point P551 (80.9718, -91.6486)
  point P556 (80.9718, -91.6486)
  point P560 (114.8064, -54.2219)
  point P561 (114.8064, -54.2219)
  point P563 (120.321, -56.8264)
  point P577 (120.321, -56.8264)
  point P558 (114.8064, -54.2219)
  point P566 (114.8064, -54.2219)
  point P568 (82.4994, -90.121)
  point P572 (82.4994, -90.121)
  point P573 (84.8512, -92.69)
  point P575 (84.8512, -92.69)
  point P571 (82.4994, -90.121)
  point P576 (82.4994, -90.121)
  point P580 (115.5378, -57.0826)
  point P581 (115.5378, -57.0826)
  point P583 (118.5771, -58.5842)
  point P587 (118.5771, -58.5842)
  point P578 (115.5378, -57.0826)
  point P586 (115.5378, -57.0826)
  point P590 (113.8497, -58.7707)
  point P591 (113.8497, -58.7707)
  point P593 (116.8538, -60.3215)
  point P607 (116.8538, -60.3215)
  point P588 (113.8497, -58.7707)
  point P596 (113.8497, -58.7707)
  point P598 (87.0719, -85.5485)
  point P602 (87.0719, -85.5485)
  point P603 (89.5188, -87.9526)
  point P605 (89.5188, -87.9526)
  point P601 (87.0719, -85.5485)
  point P606 (87.0719, -85.5485)
  point P610 (84.0247, -88.5957)
  point P611 (84.0247, -88.5957)
  point P613 (86.4082, -91.1089)
  point P627 (86.4082, -91.1089)
  point P608 (84.0247, -88.5957)
  point P616 (84.0247, -88.5957)
  point P618 (112.1805, -60.4399)
  point P622 (112.1805, -60.4399)
  point P623 (115.1499, -62.0397)
  point P625 (115.1499, -62.0397)
  point P621 (112.1805, -60.4399)
  point P626 (112.1805, -60.4399)
  point P630 (110.5289, -62.0915)
  point P631 (110.5289, -62.0915)
  point P633 (113.4639, -63.7403)
  point P647 (113.4639, -63.7403)
  point P628 (110.5289, -62.0915)
  point P636 (110.5289, -62.0915)
  point P638 (83.7683, -85.26)
  point P642 (83.7683, -85.26)
  point P643 (87.9637, -89.5301)
  point P645 (87.9637, -89.5301)
  point P641 (83.7683, -85.26)
  point P646 (83.7683, -85.26)
  point P650 (88.5957, -84.0247)
  point P651 (88.5957, -84.0247)
  point P653 (91.0743, -86.3754)
  point P667 (91.0743, -86.3754)
  point P648 (88.5957, -84.0247)
  point P656 (88.5957, -84.0247)
  point P658 (106.6276, -62.4007)
  point P662 (106.6276, -62.4007)
  point P663 (111.7946, -65.4246)
  point P665 (111.7946, -65.4246)
  point P661 (106.6276, -62.4007)
  point P666 (106.6276, -62.4007)
  point P670 (90.121, -82.4994)
  point P671 (90.121, -82.4994)
  point P673 (92.6313, -84.7975)
  point P687 (92.6313, -84.7975)
  point P668 (90.121, -82.4994)
  point P676 (90.121, -82.4994)
  point P678 (107.2733, -65.3471)
  point P682 (107.2733, -65.3471)
  point P683 (110.1405, -67.0938)
  point P685 (110.1405, -67.0938)
  point P681 (107.2733, -65.3471)
  point P686 (107.2733, -65.3471)
  point P690 (105.6668, -66.9536)
  point P691 (105.6668, -66.9536)
  point P693 (108.5006, -68.7492)
  point P707 (108.5006, -68.7492)
  point P688 (105.6668, -66.9536)
  point P696 (105.6668, -66.9536)
  point P698 (91.6486, -80.9718)
  point P702 (91.6486, -80.9718)
  point P703 (94.1908, -83.2178)
  point P705 (94.1908, -83.2178)
  point P701 (91.6486, -80.9718)
  point P706 (91.6486, -80.9718)
  point P710 (104.073, -68.5474)
  point P711 (104.073, -68.5474)
  point P713 (106.8737, -70.3921)
  point P727 (106.8737, -70.3921)
  point P708 (104.073, -68.5474)
  point P716 (104.073, -68.5474)
  point P718 (91.2406, -77.7877)
  point P722 (91.2406, -77.7877)
  point P723 (95.7536, -81.6353)
  point P725 (95.7536, -81.6353)
  point P721 (91.2406, -77.7877)
  point P726 (91.2406, -77.7877)
  point P730 (94.7149, -77.9055)
  point P731 (94.7149, -77.9055)
  point P733 (97.3208, -80.049)
  point P747 (97.3208, -80.049)
  point P728 (94.7149, -77.9055)
  point P736 (94.7149, -77.9055)
  point P738 (102.4907, -70.1297)
  point P742 (102.4907, -70.1297)
  point P743 (105.2585, -72.0235)
  point P745 (105.2585, -72.0235)
  point P741 (102.4907, -70.1297)
  point P746 (102.4907, -70.1297)
  point P750 (98.8189, -70.2094)
  point P751 (98.8189, -70.2094)
  point P753 (103.654, -73.6447)
  point P767 (103.654, -73.6447)
  point P748 (98.8189, -70.2094)
  point P756 (98.8189, -70.2094)
  point P758 (96.2555, -76.3649)
  point P762 (96.2555, -76.3649)
  point P763 (98.8935, -78.4578)
  point P765 (98.8935, -78.4578)
  point P761 (96.2555, -76.3649)
  point P766 (96.2555, -76.3649)
  point P771 (74.8181, -97.8023)
  point P774 (74.8181, -97.8023)
  point P775 (77.01, -100.6676)
  point P777 (77.01, -100.6676)
  point P773 (74.8181, -97.8023)
  point P769 (74.8181, -97.8023)
  point P778 (74.8181, -97.8023)
  point P782 (73.2639, -99.3565)
  point P785 (73.2639, -99.3565)
  point P786 (75.4235, -102.2851)
  point P788 (75.4235, -102.2851)
  point P784 (73.2639, -99.3565)
  point P780 (73.2639, -99.3565)
  point P789 (73.2639, -99.3565)
  point P793 (71.7015, -100.9189)
  point P796 (71.7015, -100.9189)
  point P797 (73.8285, -103.9127)
  point P799 (73.8285, -103.9127)
  point P795 (71.7015, -100.9189)
  point P791 (71.7015, -100.9189)
  point P800 (71.7015, -100.9189)
  point P804 (68.6703, -100.358)
  point P807 (68.6703, -100.358)
  point P808 (72.224, -105.5515)
  point P810 (72.224, -105.5515)
  point P806 (68.6703, -100.358)
  point P802 (68.6703, -100.358)
  point P811 (68.6703, -100.358)
  point P815 (68.5474, -104.073)
  point P818 (68.5474, -104.073)
  point P819 (70.6088, -107.2028)
  point P821 (70.6088, -107.2028)
  point P817 (68.5474, -104.073)
  point P813 (68.5474, -104.073)
  point P822 (68.5474, -104.073)
  point P826 (66.9536, -105.6668)
  point P829 (66.9536, -105.6668)
  point P830 (68.9819, -108.8678)
  point P832 (68.9819, -108.8678)
  point P828 (66.9536, -105.6668)
  point P824 (66.9536, -105.6668)
  point P833 (66.9536, -105.6668)
  point P837 (65.3471, -107.2733)
  point P840 (65.3471, -107.2733)
  point P841 (67.342, -110.548)
  point P843 (67.342, -110.548)
  point P839 (65.3471, -107.2733)
  point P835 (65.3471, -107.2733)
  point P844 (65.3471, -107.2733)
  point P848 (63.7268, -108.8936)
  point P851 (63.7268, -108.8936)
  point P852 (65.6879, -112.2446)
  point P854 (65.6879, -112.2446)
  point P850 (63.7268, -108.8936)
  point P846 (63.7268, -108.8936)
  point P855 (63.7268, -108.8936)
  point P859 (60.7994, -108.2289)
  point P862 (60.7994, -108.2289)
  point P863 (63.7403, -113.4639)
  point P865 (63.7403, -113.4639)
  point P861 (60.7994, -108.2289)
  point P857 (60.7994, -108.2289)
  point P866 (60.7994, -108.2289)
  point P875 (60.4399, -112.1805)
  point P877 (60.4399, -112.1805)
  point P868 (62.0397, -115.1499)
  point P869 (62.0397, -115.1499)
  point P876 (60.4399, -112.1805)
  point P874 (60.4399, -112.1805)
  point P878 (60.4399, -112.1805)
  point P867 (60.4399, -112.1805)
  point P887 (58.7707, -113.8497)
  point P889 (58.7707, -113.8497)
  point P880 (60.3215, -116.8538)
  point P881 (60.3215, -116.8538)
  point P888 (58.7707, -113.8497)
  point P886 (58.7707, -113.8497)
  point P890 (58.7707, -113.8497)
  point P879 (58.7707, -113.8497)
  point P899 (57.0826, -115.5378)
  point P901 (57.0826, -115.5378)
  point P892 (58.5842, -118.5771)
  point P893 (58.5842, -118.5771)
  point P900 (57.0826, -115.5378)
  point P898 (57.0826, -115.5378)
  point P902 (57.0826, -115.5378)
  point P891 (57.0826, -115.5378)
  point P911 (55.3742, -117.2462)
  point P913 (55.3742, -117.2462)
  point P904 (56.8264, -120.321)
  point P905 (56.8264, -120.321)
  point P912 (55.3742, -117.2462)
  point P910 (55.3742, -117.2462)
  point P914 (55.3742, -117.2462)
  point P903 (55.3742, -117.2462)
  point P923 (52.5278, -116.5005)
  point P925 (52.5278, -116.5005)
  point P916 (55.0467, -122.0871)
  point P917 (55.0467, -122.0871)
  point P924 (52.5278, -116.5005)
  point P922 (52.5278, -116.5005)
  point P926 (52.5278, -116.5005)
  point P915 (52.5278, -116.5005)
  point P935 (51.8906, -120.7298)
  point P937 (51.8906, -120.7298)
  point P928 (53.2434, -123.8771)
  point P929 (53.2434, -123.8771)
  point P936 (51.8906, -120.7298)
  point P934 (51.8906, -120.7298)
  point P938 (51.8906, -120.7298)
  point P927 (51.8906, -120.7298)
  point P947 (50.1124, -122.508)
  point P949 (50.1124, -122.508)
  point P940 (51.4149, -125.6923)
  point P941 (51.4149, -125.6923)
  point P948 (50.1124, -122.508)
  point P946 (50.1124, -122.508)
  point P950 (50.1124, -122.508)
  point P939 (50.1124, -122.508)
  point P959 (48.3075, -124.3129)
  point P961 (48.3075, -124.3129)
  point P952 (49.5595, -127.5347)
  point P953 (49.5595, -127.5347)
  point P960 (48.3075, -124.3129)
  point P958 (48.3075, -124.3129)
  point P962 (48.3075, -124.3129)
  point P951 (48.3075, -124.3129)
  point P971 (46.4745, -126.1459)
  point P973 (46.4745, -126.1459)
  point P964 (47.6755, -129.4059)
  point P965 (47.6755, -129.4059)
  point P972 (46.4745, -126.1459)
  point P970 (46.4745, -126.1459)
  point P974 (46.4745, -126.1459)
  point P963 (46.4745, -126.1459)
  point P977 (43.6829, -125.3453)
  point P979 (43.6829, -125.3453)
  point P980 (45.7609, -131.3079)
  point P982 (45.7609, -131.3079)
  point P983 (42.716, -129.9044)
  point P985 (42.716, -129.9044)
  point P987 (43.8137, -133.2426)
  point P990 (43.8137, -133.2426)
  point P991 (40.7867, -131.8337)
  point P993 (40.7867, -131.8337)
  point P995 (41.8319, -135.2121)
  point P998 (41.8319, -135.2121)
  point P999 (38.8211, -133.7993)
  point P1001 (38.8211, -133.7993)
  point P1003 (39.8132, -137.2186)
  point P1006 (39.8132, -137.2186)
  point P1007 (36.8169, -135.8035)
  point P1009 (36.8169, -135.8035)
  point P1011 (37.7552, -139.2644)
  point P1014 (37.7552, -139.2644)
  point P1015 (34.0482, -134.9801)
  point P1017 (34.0482, -134.9801)
  point P1019 (35.6555, -141.3521)
  point P1022 (35.6555, -141.3521)
  point P1023 (32.6831, -139.9373)
  point P1025 (32.6831, -139.9373)
  point P1027 (33.5115, -143.4843)
  point P1030 (33.5115, -143.4843)
  point P1031 (30.548, -142.0724)
  point P1033 (30.548, -142.0724)
  point P1035 (31.3202, -145.6638)
  point P1038 (31.3202, -145.6638)
  point P1039 (28.3637, -144.2567)
  point P1041 (28.3637, -144.2567)
  point P1043 (29.0788, -147.8935)
  point P1046 (29.0788, -147.8935)
  point P1047 (26.127, -146.4934)
  point P1049 (26.127, -146.4934)
  point P1051 (26.784, -150.1768)
  point P1054 (26.784, -150.1768)
  point P1055 (23.3386, -145.6897)
  point P1057 (23.3386, -145.6897)
  point P1059 (24.4323, -152.5169)
  point P1062 (24.4323, -152.5169)
  point P1063 (21.4828, -151.1376)
  point P1065 (21.4828, -151.1376)
  point P1067 (22.0201, -154.9176)
  point P1070 (22.0201, -154.9176)
  point P1071 (19.0679, -153.5525)
  point P1073 (19.0679, -153.5525)
  point P1075 (19.5435, -157.3828)
  point P1078 (19.5435, -157.3828)
  point P1079 (16.5856, -156.0348)
  point P1081 (16.5856, -156.0348)
  point P1083 (16.9982, -159.9168)
  point P1086 (16.9982, -159.9168)
  point P1087 (14.0314, -158.589)
  point P1089 (14.0314, -158.589)
  point P1091 (14.3796, -162.5241)
  point P1094 (14.3796, -162.5241)
  point P1095 (11.1634, -157.8649)
  point P1097 (11.1634, -157.8649)
  point P1099 (11.6828, -165.2096)
  point P1102 (11.6828, -165.2096)
  point P1103 (8.688, -163.9324)
  point P1105 (8.688, -163.9324)
  point P1107 (8.9025, -167.9787)
  point P1110 (8.9025, -167.9787)
  point P1111 (5.8879, -166.7325)
  point P1113 (5.8879, -166.7325)
  point P1115 (6.0328, -170.8371)
  point P1118 (6.0328, -170.8371)
  point P1119 (2.9941, -169.6263)
  point P1121 (2.9941, -169.6263)
  point P1123 (3.0676, -173.7911)
  point P1126 (3.0676, -173.7911)
  point P103 (3.0564, -173.1561)
  point P1129 (3.034, -171.8861)
  coincident P6 P9
  coincident L2 P10
  coincident P9 P11
  coincident L3 P12
  coincident L4 P13
  coincident L3 P15
  coincident L3 P110
  coincident L3 P111
  coincident L3 P112
  coincident L3 P113
  coincident L3 P114
  coincident L3 P115
  coincident L3 P116
  coincident L3 P117
  coincident L3 P118
  coincident L3 P119
  coincident L3 P120
  coincident L3 P121
  coincident L3 P122
  coincident L3 P123
  coincident L3 P124
  coincident L3 P125
  coincident L3 P126
  coincident L3 P127
  coincident L3 P128
  coincident L3 P129
  coincident L3 P130
  coincident L3 P131
  coincident L3 P132
  coincident L3 P133
  coincident L3 P134
  coincident L3 P135
  coincident L3 P136
  coincident L3 P137
  coincident L3 P138
  coincident L3 P139
  coincident L3 P140
  coincident L3 P141
  coincident L3 P142
  coincident L3 P143
  coincident L3 P144
  coincident L3 P145
  coincident L3 P146
  coincident L3 P147
  coincident L3 P148
  coincident L3 P149
  coincident L3 P150
  coincident L3 P151
  coincident L3 P152
  coincident L3 P153
  coincident L3 P154
  coincident L3 P155
  coincident L3 P156
  coincident L3 P157
  coincident L3 P158
  coincident L3 P159
  coincident L3 P160
  coincident L3 P161
  coincident L3 P162
  coincident L3 P163
  coincident L3 P164
  coincident L3 P165
  coincident L3 P166
  coincident L3 P167
  coincident L3 P168
  coincident L3 P169
  coincident L3 P170
  coincident L3 P171
  coincident L3 P172
  coincident L3 P173
  coincident L3 P174
  coincident L3 P175
  coincident L3 P176
  coincident L3 P177
  coincident L3 P178
  coincident L3 P179
  coincident L3 P180
  coincident L3 P181
  coincident L3 P182
  coincident L3 P183
  coincident L3 P184
  coincident L3 P185
  coincident L3 P186
  coincident L3 P187
  coincident L3 P188
  coincident L3 P189
  coincident L3 P190
  coincident L3 P191
  coincident L3 P192
  coincident L3 P193
  coincident L3 P194
  coincident L3 P195
  coincident L95 P196
  parallel L6 L97
  coincident L95 P197
  parallel L7 L98
  coincident L95 P198
  parallel L8 L99
  coincident L95 P199
  parallel L9 L100
  coincident L96 P200
  parallel L10 L101
  coincident L95 P201
  parallel L11 L102
  coincident L95 P202
  parallel L12 L103
  coincident L95 P203
  parallel L13 L104
  coincident L95 P204
  parallel L14 L105
  coincident L96 P205
  parallel L15 L106
  coincident L95 P206
  parallel L16 L107
  coincident L95 P207
  parallel L17 L108
  coincident L95 P208
  parallel L18 L109
  coincident L95 P209
  parallel L19 L110
  coincident L96 P210
  parallel L20 L111
  coincident L95 P211
  parallel L21 L112
  coincident L95 P212
  parallel L22 L113
  coincident L95 P213
  parallel L23 L114
  coincident L95 P214
  parallel L24 L115
  coincident L96 P215
  parallel L25 L116
  coincident L95 P216
  parallel L26 L117
  coincident L95 P217
  parallel L27 L118
  coincident L95 P218
  parallel L28 L119
  coincident L95 P219
  parallel L29 L120
  coincident L96 P220
  coincident L95 P221
  coincident L95 P222
  coincident L95 P223
  coincident L95 P224
  coincident L96 P225
  coincident L95 P226
  coincident L95 P227
  coincident L95 P228
  coincident L95 P229
  coincident L96 P230
  coincident L95 P231
  coincident L95 P232
  coincident L95 P233
  coincident L95 P234
  coincident L96 P235
  coincident L95 P236
  coincident L95 P237
  coincident L95 P238
  coincident L95 P239
  coincident L96 P240
  coincident L95 P241
  coincident L95 P242
  coincident L95 P243
  coincident L95 P244
  coincident L96 P245
  coincident L95 P246
  coincident L95 P247
  coincident L95 P248
  coincident L95 P249
  coincident L96 P250
  coincident L95 P251
  coincident L95 P252
  coincident L95 P253
  coincident L95 P254
  coincident L96 P255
